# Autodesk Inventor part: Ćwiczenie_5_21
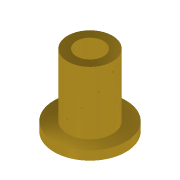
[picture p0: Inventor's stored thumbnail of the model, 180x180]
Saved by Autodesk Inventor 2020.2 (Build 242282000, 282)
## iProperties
Created: 2005-03
Part Number: Ćwiczenie_5_21
Document SubType Name: Modeling
Designer: F.Stasiak
Manufacturer: Standard
Standards Organization: Custom
Material: Złoto
Mass: 2531.42 g
Surface Area: 296.881 cm^2
Volume: 131.161 cm^3
Density: 19.3 g/cm^3
Appearance: Złoty — metal
Manager: www.cadconsulting.pl
Company: Fabian Stasiak CAD Consulting
Author: F.Stasiak
Subject: Zbiór ćwiczeń. Autodesk Inventor 2020. Kurs podstawowy
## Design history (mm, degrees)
sketch "Szkic1"
  geometry: C1 r 25 at (0, 0); C2 r 40 at (0, 0); 1 further point
  constraints: 2 centre point, 1 coincident
  dimensions: "d0" = 50 diameter of C1; "d1" = 80 diameter of C2
extrude "Wyciągnięcie proste1" new body sketch "Szkic1" distance "d2" = 80; taper "d3" = 0 deg
extrude "Wyciągnięcie proste2" join sketch "Szkic1" distance "d4" = 10; taper "d5" = 0 deg
sketch "Szkic2"
  geometry: C1 r 25 at (0, 0) reference; C2 r 15 at (0, 0)
  constraints: 1 centre point
  dimensions: "d6" = 30 diameter of C2
extrude "Wyciągnięcie proste3" cut sketch "Szkic2" extent not by distance; stored distance "d7" = 10; taper "d8" = 0 deg
node "Oś konstrukcyjna1"
node "Płaszczyzna konstrukcyjna1"
node "Płaszczyzna konstrukcyjna2"
node "Płaszczyzna konstrukcyjna3"
node "Płaszczyzna konstrukcyjna4"
sketch "Szkic3"
  geometry: L1 (10, 25)-(80, 25) reference
sketch "Szkic4"
  geometry: L1 (10, 25)-(80, 25) reference
sketch "Szkic5"
  geometry: L1 (10, 25)-(80, 25) reference
sketch "Szkic6"
  geometry: L1 (10, 25)-(80, 25) reference
node "Płaszczyzna konstrukcyjna5"
node "Płaszczyzna konstrukcyjna6"
node "Płaszczyzna konstrukcyjna7"
node "Płaszczyzna konstrukcyjna8"
node "Płaszczyzna konstrukcyjna9"
node "Płaszczyzna konstrukcyjna10"
node "Płaszczyzna konstrukcyjna11"
node "Płaszczyzna konstrukcyjna12"
node "Punkt konstrukcyjny1"
node "Punkt konstrukcyjny2"
node "Punkt konstrukcyjny3"
node "Punkt konstrukcyjny4"
node "Oś konstrukcyjna2"
node "Oś konstrukcyjna3"
node "Oś konstrukcyjna4"
node "Oś konstrukcyjna5"
node "Bryła1"
node "Korpusy bryłowe"
node "Korpusy powierzchniowe"
other parameters: "d9" = 0, "d10" = 30 deg, "d11" = 60 deg, "d12" = 90 deg, "d13" = 90 deg, "d14" = 90 deg, "d15" = 90 deg, "d16" = 90 deg, "d17" = 15, "d19" = 45
